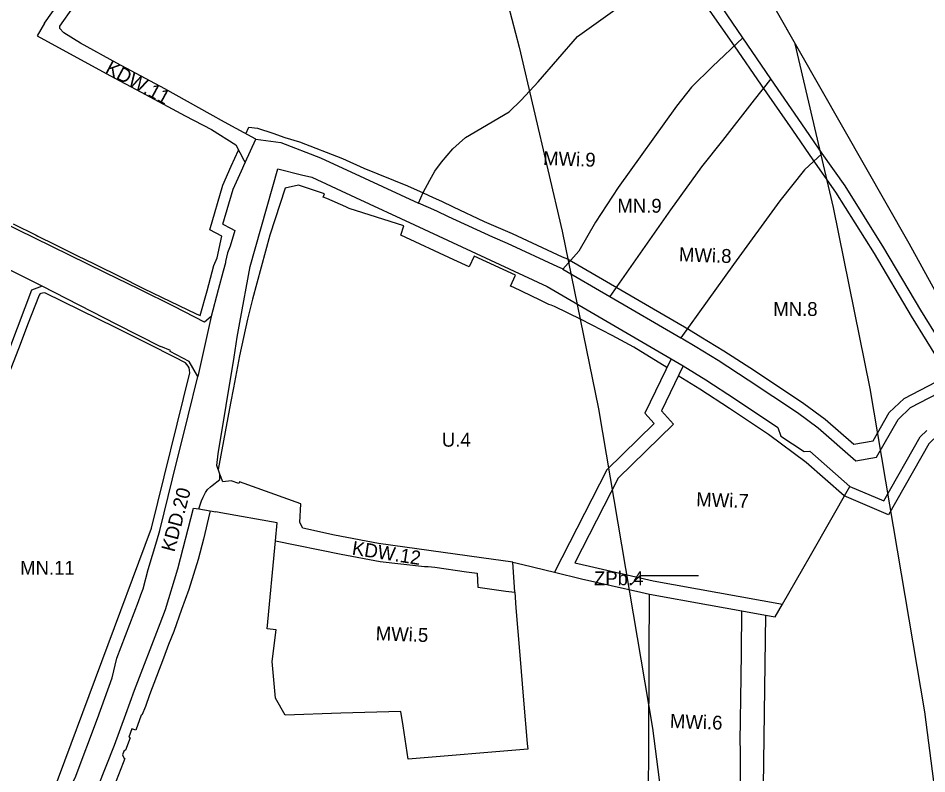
# Model space of a CAD drawing. Extents: x 7418991 to 7423142, y 5547704 to 5549547.
# Drawn here: x 7420359 to 7420686.6, y 5548009.3 to 5548281.5 of the extents above; entities that cross this region are included whole.
import ezdxf

# ---------------------------------------------------------------- set-up
doc = ezdxf.new("R2010")
doc.units = 0
for name, color, linetype in [('LIN_Linia Zabudowy Nieprzekraczalna', 7, 'Continuous'), ('LIN_linie_rozgraniczajace', 7, 'Continuous'), ('TRS_strefa ograniczen tunelu', 7, 'Continuous'), ('TXT_Oznaczenia_przeznaczen', 7, 'Continuous')]:
    doc.layers.add(name, color=color, linetype=linetype)

msp = doc.modelspace()

# ---------------------------------------------------------------- linework, layer by layer
at = {"layer": 'LIN_Linia Zabudowy Nieprzekraczalna'}
for p, q in [((7420407.03, 5548097.79), (7420420.89, 5548153.69)), ((7420357.76, 5547965.61), (7420407.03, 5548097.79))]:
    msp.add_line(p, q, dxfattribs=at)
for points in [[(7420692.35, 5548155.89), (7420681.06, 5548174.17), (7420667.7, 5548196.71), (7420653.78, 5548218.81), (7420645.64, 5548230.4), (7420638.26, 5548241.14), (7420627.02, 5548257.4), (7420617.3, 5548271.58), (7420598.03, 5548299.02)], [(7420441.12, 5548239.83), (7420442.22, 5548242.27), (7420445.35, 5548241.85), (7420450.83, 5548240.02), (7420455.18, 5548238.53), (7420460.49, 5548236.91), (7420475.9, 5548230.89), (7420483.67, 5548227.48), (7420499.34, 5548221.03), (7420504.98, 5548218.52), (7420508.6, 5548216.88), (7420511.59, 5548215.53), (7420515.88, 5548213.52), (7420526.97, 5548208.26), (7420537.07, 5548203.89), (7420555.15, 5548195.56), (7420557.06, 5548194.74), (7420600.63, 5548169.45), (7420605.11, 5548166.73), (7420613.47, 5548161.66), (7420624.43, 5548154.54), (7420642.23, 5548142.67), (7420649.92, 5548137.06), (7420660.26, 5548128), (7420667.22, 5548129.17), (7420673.09, 5548139.47), (7420678.43, 5548144.48), (7420690.03, 5548150.52)], [(7420357.19, 5548207.4), (7420365.46, 5548203.28), (7420366.11, 5548202.95), (7420372.19, 5548199.96), (7420380.45, 5548195.86), (7420386.17, 5548193.09), (7420396.64, 5548187.89), (7420402.98, 5548184.69), (7420404.24, 5548184.09), (7420410.72, 5548180.96), (7420423.16, 5548174.94), (7420424.66, 5548174.32), (7420427.14, 5548183.23), (7420429.59, 5548192.44), (7420430.77, 5548195.19), (7420432.38, 5548202.98), (7420428.06, 5548205.29), (7420432.77, 5548221.27), (7420435.84, 5548228.14), (7420438.45, 5548233.93)], [(7420592.88, 5548155.65), (7420580.97, 5548162.96), (7420573.13, 5548167.21), (7420562.03, 5548172.9), (7420552.4, 5548177.63), (7420551.17, 5548178.1), (7420550.27, 5548178.39), (7420547.24, 5548179.94), (7420537.48, 5548184.55), (7420536.56, 5548184.98), (7420538.36, 5548188.91), (7420523.41, 5548195.78), (7420521.62, 5548191.88), (7420516.06, 5548194.45), (7420496.95, 5548203.29), (7420498.03, 5548206.73), (7420478.32, 5548212.93), (7420477.17, 5548213.51), (7420470.24, 5548216.53), (7420468.98, 5548217.05), (7420469.39, 5548218.26), (7420460.12, 5548221.35), (7420455.25, 5548220.24), (7420449.76, 5548203.34), (7420443.44, 5548180.24), (7420441.64, 5548173.04), (7420438.86, 5548159.84), (7420436.61, 5548148.33), (7420435.61, 5548142.75), (7420431.13, 5548118.88)], [(7420368.86, 5548182.46), (7420368.52, 5548182.5), (7420367.76, 5548182.46), (7420367.22, 5548182.33), (7420366.84, 5548182.12), (7420366.82, 5548182.1), (7420366.62, 5548181.75), (7420362.34, 5548171.05), (7420359.73, 5548163.94), (7420354.9, 5548151.56)], [(7420395.09, 5548169.59), (7420394.05, 5548170.08), (7420368.86, 5548182.46)], [(7420406.09, 5548164), (7420395.09, 5548169.59)], [(7420419.39, 5548157.32), (7420415.39, 5548159.36), (7420406.09, 5548164)], [(7420420.89, 5548153.69), (7420420.79, 5548154.7), (7420420.6, 5548155.47), (7420420.26, 5548156.13), (7420419.39, 5548157.32)], [(7420826.38, 5547969.48), (7420824.89, 5547971), (7420816.06, 5547982.21), (7420785.87, 5548015.55), (7420781.84, 5548020.01), (7420777.28, 5548024.67), (7420754.72, 5548043.42), (7420743.04, 5548063.92), (7420731.92, 5548084.98), (7420718.82, 5548106.54), (7420704.88, 5548134.1), (7420700.29, 5548135.57), (7420688.95, 5548129.66), (7420687.39, 5548128.19), (7420672.76, 5548102.54), (7420656.75, 5548109.36), (7420643.05, 5548121.37), (7420629.56, 5548131.5), (7420615.46, 5548140.9), (7420604.78, 5548147.83), (7420596.96, 5548152.58)], [(7420428.26, 5548103.98), (7420428.16, 5548103.57), (7420425.82, 5548093.83), (7420423.85, 5548086.5), (7420420.53, 5548075.7), (7420417.93, 5548068.43), (7420415.09, 5548060.51), (7420413.26, 5548055.81), (7420411.44, 5548050.89), (7420406.4, 5548037.66)], [(7420406.4, 5548037.66), (7420404.88, 5548033.52), (7420403.61, 5548030.35)], [(7420403.61, 5548030.35), (7420403.4, 5548030.43), (7420401.43, 5548025.01), (7420400.01, 5548025.52), (7420398.85, 5548022.43), (7420399.37, 5548022.24), (7420397.7, 5548017.79), (7420397.04, 5548017.45), (7420396.56, 5548016.14), (7420397.18, 5548014.81), (7420397.43, 5548014.72)], [(7420397.43, 5548014.72), (7420396.85, 5548013.25), (7420391.77, 5548000.28), (7420390.82, 5547997.82)]]:
    msp.add_lwpolyline(points, dxfattribs=at)
at = {"layer": 'LIN_linie_rozgraniczajace'}
for p, q in [((7420453.67, 5548236.69), (7420468.05, 5548231.15)), ((7420428.58, 5548173.96), (7420423.83, 5548152.38)), ((7420594.41, 5548158.81), (7420584.94, 5548139.21)), ((7420680.77, 5548141.18), (7420695.95, 5548149.1)), ((7420660.99, 5548122.04), (7420668.48, 5548123.29)), ((7420571.25, 5548118.81), (7420552.34, 5548081.9)), ((7420658.91, 5548112.79), (7420671.05, 5548107.62)), ((7420451.76, 5548093.16), (7420475.5, 5548088.44)), ((7420541.01, 5548084.64), (7420552.34, 5548081.9)), ((7420541.15, 5548035.84), (7420542.55, 5548020.15))]:
    msp.add_line(p, q, dxfattribs=at)
for points in [[(7420438.43, 5548499.09), (7420436.57, 5548471.43), (7420436.07, 5548464.08), (7420434.35, 5548438.55), (7420461.53, 5548424.61), (7420477.91, 5548414.57), (7420492.78, 5548405.41), (7420519.26, 5548389.1), (7420548.5, 5548366.71), (7420560.25, 5548358.05), (7420568.7, 5548351.61), (7420580.26, 5548342.08), (7420597.79, 5548325.09), (7420604.35, 5548319.1), (7420606.03, 5548317.56), (7420609.48, 5548313.8), (7420611.83, 5548311.24), (7420632.33, 5548284.25), (7420680.09, 5548200.38), (7420703.55, 5548157.78)], [(7420368.53, 5548279.65), (7420369.13, 5548280.52), (7420394.07, 5548315.91), (7420398.15, 5548313.14), (7420383.79, 5548292.65), (7420373.91, 5548278.55), (7420373.93, 5548277.94)], [(7420503.35, 5548214.79), (7420505.05, 5548218.68), (7420507.4, 5548223.12), (7420509.27, 5548226.37), (7420511.6, 5548229.63), (7420515.67, 5548234.43), (7420520.3, 5548238.47), (7420536.05, 5548247.72), (7420540.34, 5548251.9), (7420546.51, 5548258.56), (7420560.71, 5548274.89), (7420575.02, 5548285.1), (7420587.86, 5548292.27), (7420601.36, 5548301.23), (7420602.39, 5548301.92)], [(7420698.13, 5548154.14), (7420684.48, 5548176.24), (7420671.11, 5548198.8), (7420657.11, 5548221.03), (7420648.92, 5548232.68), (7420641.55, 5548243.41), (7420630.32, 5548259.67), (7420620.24, 5548274.37), (7420614.65, 5548282.71), (7420608.78, 5548291.44), (7420605.02, 5548297.38), (7420605.58, 5548297.78), (7420603.55, 5548300.79), (7420602.39, 5548301.92)], [(7420426.22, 5548171.99), (7420415.22, 5548177.66), (7420402.67, 5548183.82), (7420390.43, 5548189.74), (7420377.56, 5548196.15), (7420364.97, 5548202.2), (7420352.34, 5548208.3), (7420339.71, 5548214.44), (7420327.19, 5548220.68), (7420314.67, 5548226.85), (7420302.07, 5548233.01), (7420300.21, 5548233.96), (7420289.57, 5548239.37), (7420273.14, 5548247.62), (7420271.3, 5548245.54), (7420250.38, 5548256.86), (7420246.18, 5548259.13), (7420244.57, 5548259.84), (7420230.05, 5548267.75), (7420220.41, 5548272.9), (7420206.86, 5548279.87), (7420200.41, 5548283.37)], [(7420368.53, 5548279.65), (7420365.8, 5548275.18), (7420392.06, 5548260.78), (7420403.4, 5548254.79), (7420419.22, 5548246.32), (7420428.67, 5548241.4), (7420437.45, 5548235.83), (7420440.34, 5548230.35), (7420440.82, 5548229.44)], [(7420444.64, 5548237.91), (7420433.45, 5548244.02), (7420428.17, 5548246.91), (7420411.88, 5548256.08), (7420394.62, 5548265.28), (7420381.49, 5548272.51), (7420375.45, 5548276.25), (7420373.93, 5548277.94)], [(7420620.24, 5548274.37), (7420609.39, 5548264.08), (7420601.72, 5548256.59), (7420596.35, 5548249.73), (7420575.31, 5548220.52), (7420567.15, 5548208.04), (7420561.19, 5548197.5), (7420555.43, 5548191.06)], [(7420630.32, 5548259.67), (7420624.4, 5548252.01), (7420612.93, 5548237.46), (7420605.35, 5548227.91), (7420594.15, 5548212.43), (7420572.36, 5548181.23)], [(7420432.82, 5548207.28), (7420436.53, 5548219.88), (7420439.49, 5548226.5), (7420440.82, 5548229.44), (7420444.64, 5548237.91), (7420453.67, 5548236.69)], [(7420468.05, 5548231.15), (7420483.83, 5548223.8), (7420503.35, 5548214.79)], [(7420648.92, 5548232.68), (7420642.56, 5548226.88), (7420633.6, 5548215.65), (7420616.92, 5548192.73), (7420597.97, 5548166.37)], [(7420430.65, 5548120.31), (7420431.16, 5548124.51), (7420436.82, 5548159.41), (7420437.94, 5548166.51), (7420438.9, 5548171.81), (7420442.63, 5548192.07), (7420452.6, 5548227.16)], [(7420452.6, 5548227.16), (7420461.16, 5548225.07), (7420464.83, 5548224.24)], [(7420464.83, 5548224.24), (7420480.62, 5548216.88), (7420501.85, 5548207.08), (7420549.7, 5548184.76)], [(7420423.83, 5548152.38), (7420420.69, 5548157.85), (7420413.79, 5548161.36), (7420413.95, 5548161.81), (7420410.47, 5548163.15), (7420410.44, 5548163.06), (7420394.61, 5548171.11), (7420367.61, 5548184.98), (7420352.75, 5548192.43), (7420335.33, 5548200.95), (7420317.69, 5548209.94), (7420307.76, 5548214.65), (7420300.94, 5548217.98)], [(7420555.26, 5548191.16), (7420553.53, 5548191.9), (7420535.4, 5548200.25), (7420530.15, 5548202.65), (7420514.2, 5548209.89), (7420509.92, 5548211.9), (7420506.99, 5548213.22), (7420503.35, 5548214.79)], [(7420432.82, 5548207.28), (7420435.57, 5548205.81), (7420437.12, 5548204.98), (7420435.39, 5548199.38), (7420434.5, 5548196.94), (7420433.78, 5548193.87), (7420433.73, 5548193.33), (7420432.94, 5548190.39), (7420431.16, 5548183.58), (7420428.58, 5548173.96), (7420426.22, 5548171.99)], [(7420555.26, 5548191.16), (7420555.43, 5548191.06), (7420572.36, 5548181.23), (7420597.97, 5548166.37)], [(7420367.61, 5548184.98), (7420363.85, 5548183.55), (7420356.29, 5548163.48), (7420348.77, 5548144.11), (7420341.23, 5548124.28), (7420333.55, 5548104.71), (7420325.82, 5548085.01), (7420318.33, 5548065.62), (7420310.19, 5548046.16), (7420301.68, 5548027.06), (7420293.66, 5548031.55), (7420291.07, 5548033), (7420296.01, 5548042.62), (7420300.29, 5548051.94)], [(7420549.7, 5548184.76), (7420594.41, 5548158.81)], [(7420597.97, 5548166.37), (7420598.59, 5548166.01), (7420603.03, 5548163.32), (7420611.34, 5548158.27), (7420622.24, 5548151.19), (7420639.94, 5548139.39), (7420647.42, 5548133.94), (7420660.99, 5548122.04)], [(7420594.41, 5548158.81), (7420598.71, 5548156.2), (7420606.91, 5548151.22), (7420617.66, 5548144.24), (7420632.93, 5548134.06), (7420633.97, 5548130.89), (7420642.33, 5548125.34), (7420644.47, 5548125.45), (7420658.91, 5548112.79)], [(7420598.71, 5548156.2), (7420590.9, 5548140.05), (7420595.27, 5548135.17), (7420575.32, 5548115.8), (7420559.68, 5548085.26), (7420564.96, 5548084.01), (7420587.94, 5548078.84), (7420634.56, 5548070.36), (7420641.88, 5548083.1), (7420644.65, 5548087.94), (7420658.91, 5548112.79)], [(7420369.89, 5547982.87), (7420378.84, 5548006.53), (7420379.5, 5548007.84), (7420387.56, 5548029.15), (7420392.91, 5548043.82), (7420394.63, 5548050.94), (7420402.34, 5548071.39), (7420403.27, 5548073.77), (7420404.07, 5548075.91), (7420405.93, 5548082.82), (7420408.96, 5548093.17), (7420410.08, 5548096.92), (7420414.66, 5548115.51), (7420420.33, 5548138.21), (7420423.83, 5548152.38)], [(7420668.48, 5548123.29), (7420676.27, 5548136.96), (7420680.77, 5548141.18)], [(7420571.25, 5548118.81), (7420588.34, 5548135.41), (7420584.94, 5548139.21)], [(7420671.05, 5548107.62), (7420684.21, 5548130.7), (7420686.61, 5548132.95)], [(7420432.75, 5548114.49), (7420431.68, 5548117.23), (7420430.65, 5548120.31)], [(7420424.15, 5548104.67), (7420425.09, 5548107.56), (7420425.68, 5548108.92), (7420426.5, 5548110.63), (7420427.32, 5548111.64), (7420428.29, 5548112.7), (7420428.91, 5548113.18), (7420431.74, 5548115.23), (7420431.68, 5548117.23)], [(7420461.58, 5548097.73), (7420460.61, 5548099.81), (7420460.96, 5548106.47), (7420438.8, 5548114.5), (7420438.57, 5548113.87), (7420435.83, 5548114.8), (7420432.75, 5548114.49)], [(7420412.12, 5548068.49), (7420416.58, 5548083.14), (7420422.24, 5548104.99)], [(7420422.24, 5548104.99), (7420424.15, 5548104.67), (7420430.21, 5548103.66)], [(7420451.76, 5548093.16), (7420452.38, 5548099.7), (7420432.02, 5548103.27), (7420430.21, 5548103.66)], [(7420475.5, 5548088.44), (7420489.47, 5548085.7), (7420505.46, 5548083.98), (7420506.83, 5548083.97), (7420509.19, 5548083.65), (7420520.63, 5548082.05), (7420524.47, 5548081.51), (7420524.77, 5548076.53), (7420534.86, 5548075.1), (7420538.11, 5548074.64), (7420537.39, 5548085.53), (7420526.04, 5548087.03), (7420488.86, 5548092.25), (7420473.08, 5548095.26), (7420461.58, 5548097.73)], [(7420542.55, 5548020.15), (7420542.73, 5548018.13), (7420499.56, 5548014.55), (7420497.82, 5548026.52), (7420497.02, 5548031.74), (7420475.3, 5548031.06), (7420455.32, 5548030.37), (7420451.72, 5548036.46), (7420450.52, 5548049.67), (7420452.08, 5548061.15), (7420448.76, 5548061.44), (7420451.76, 5548093.16)], [(7420537.39, 5548085.53), (7420541.01, 5548084.64)], [(7420552.34, 5548081.9), (7420562.15, 5548079.52), (7420583.46, 5548074.73), (7420586.66, 5548073.99)], [(7420538.11, 5548074.64), (7420538.48, 5548069.04), (7420539.85, 5548051.98), (7420541.15, 5548035.84)], [(7420610.97, 5547968.11), (7420611.41, 5547969.67), (7420600.58, 5547972.74), (7420590.12, 5547976.05), (7420586.3, 5547977.27), (7420586.32, 5548000.43), (7420586.33, 5548020.45), (7420586.34, 5548021.4), (7420586.47, 5548047.7), (7420586.49, 5548051.94), (7420586.49, 5548052.2), (7420586.66, 5548073.99), (7420607.92, 5548070.15), (7420619.96, 5548067.94)], [(7420628.5, 5548066.38), (7420631.92, 5548065.76), (7420634.56, 5548070.36)], [(7420372.77, 5547955.69), (7420370.76, 5547958.96), (7420380.13, 5547983.28), (7420387.72, 5548004.49), (7420393.75, 5548019.61), (7420397.8, 5548030.73), (7420400.96, 5548039.4), (7420410.18, 5548063.4), (7420412.12, 5548068.49)], [(7420615.54, 5547903.56), (7420618.4, 5547909.99), (7420618.78, 5547949.64), (7420618.96, 5547968.04), (7420619.44, 5548012.05), (7420619.46, 5548017.9), (7420619.32, 5548020.93), (7420619.68, 5548044.2), (7420619.81, 5548052.93), (7420619.96, 5548067.94), (7420628.5, 5548066.38), (7420627.45, 5547995.97), (7420627.21, 5547901.4), (7420626.96, 5547898.1)]]:
    msp.add_lwpolyline(points, dxfattribs=at)
at = {"layer": 'TRS_strefa ograniczen tunelu'}
for points in [[(7420505.97, 5548397.28), (7420521.12, 5548341.79), (7420539.66, 5548271.1), (7420555.19, 5548204.71), (7420568.21, 5548140.79), (7420587.66, 5548025.67), (7420594.04, 5547976.4), (7420597.15, 5547951.42), (7420609.27, 5547815.84), (7420612.79, 5547774.96)], [(7420505.97, 5548397.28), (7420519.26, 5548389.1), (7420548.5, 5548366.71), (7420560.25, 5548358.05), (7420568.7, 5548351.61), (7420580.26, 5548342.08), (7420597.79, 5548325.09), (7420604.35, 5548319.1), (7420606.03, 5548317.56), (7420609.48, 5548313.8), (7420611.83, 5548311.24), (7420632.33, 5548284.25), (7420639.17, 5548272.24)], [(7420713.56, 5547752.53), (7420707.81, 5547819.34), (7420695.62, 5547955.67), (7420692.42, 5547981.44), (7420685.92, 5548031.57), (7420666.24, 5548148.12), (7420652.97, 5548213.26), (7420639.17, 5548272.24)]]:
    msp.add_lwpolyline(points, dxfattribs=at)
at = {"layer": 'TXT_Oznaczenia_przeznaczen'}
msp.add_lwpolyline([(7420580.03, 5548077.42), (7420583.23, 5548080.72), (7420604.33, 5548080.72)], dxfattribs=at)

# ---------------------------------------------------------------- texts
for s, rotation, p in [('KDW.11', 331.6908, (7420390.05, 5548262.01)), ('MWi.9', 357.9964, (7420548.19, 5548228.6)), ('MWi.8', 357.9964, (7420597.17, 5548193.92)), ('KDD.20', 75.2333, (7420415.34, 5548088.92)), ('MWi.7', 357.9964, (7420603.41, 5548105.67)), ('KDW.12', 351.2127, (7420479.14, 5548088.26)), ('MWi.5', 357.9964, (7420487.85, 5548057.39)), ('MWi.6', 357.9964, (7420593.91, 5548025.8))]:
    msp.add_text(s, height=5, rotation=rotation, dxfattribs=at).set_placement(p)
for s, p in [('MN.9', (7420575.03, 5548211.41)), ('MN.8', (7420631.24, 5548174.2)), ('U.4', (7420511.76, 5548127.11)), ('MN.11', (7420359.7, 5548080.98)), ('ZPb.4', (7420566.59, 5548077.21))]:
    msp.add_text(s, height=5, dxfattribs=at).set_placement(p)

doc.saveas('drawing.dxf')
